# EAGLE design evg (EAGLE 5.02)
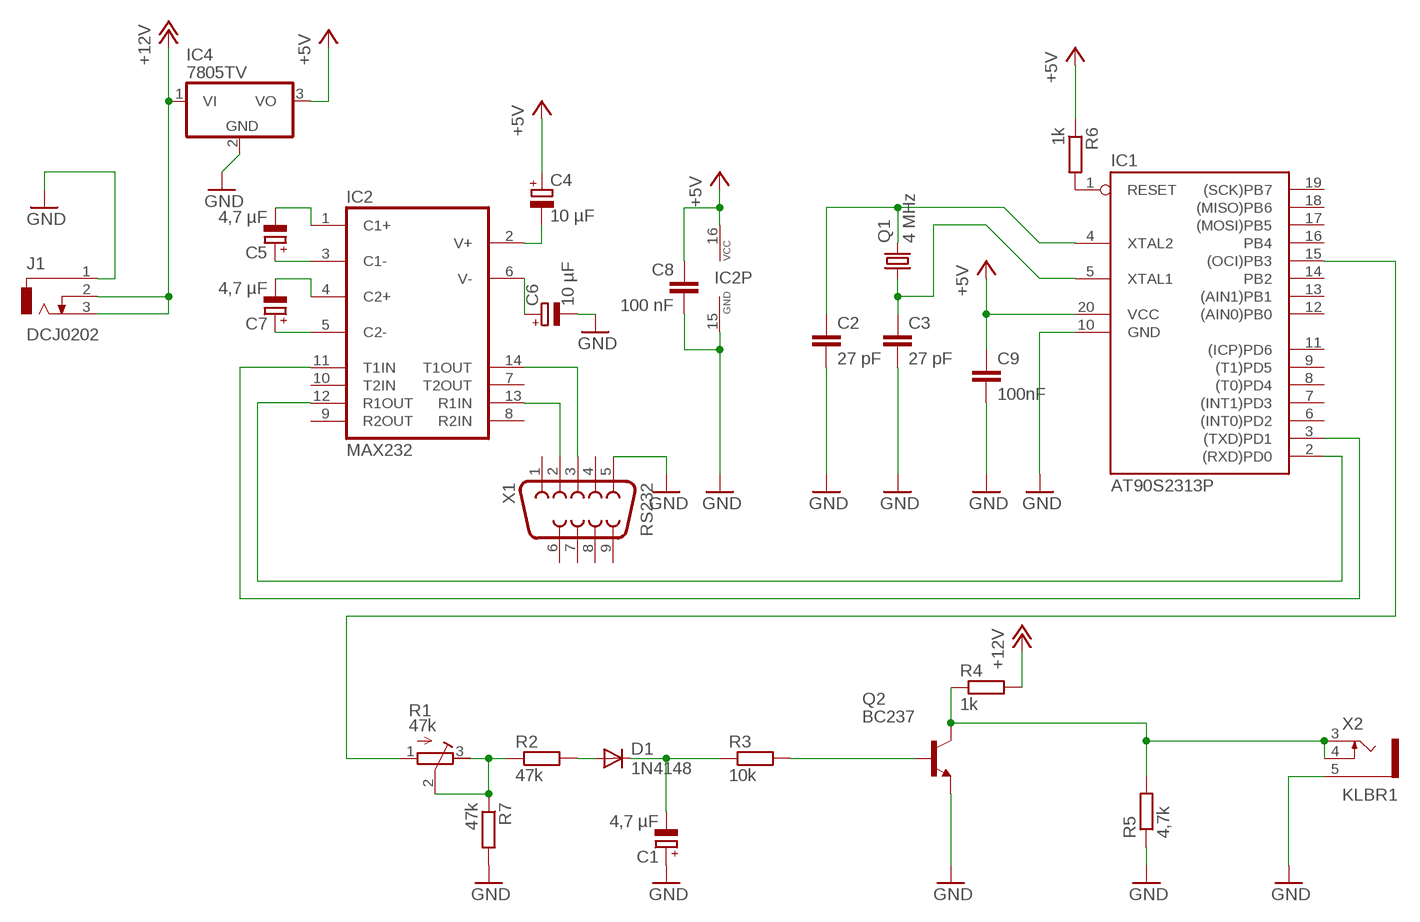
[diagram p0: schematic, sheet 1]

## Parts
C1  4,7 µF  CPOL-EUE2.5-6  [E2,5-6]
C2  27 pF  C-EU075-032X103  [C075-032X103]
C3  27 pF  C-EU075-032X103  [C075-032X103]
C4  10 µF  CPOL-EUE2.5-6  [E2,5-6]
C5  4,7 µF  CPOL-EUE2.5-6  [E2,5-6]
C6  10 µF  CPOL-EUE2.5-6  [E2,5-6]
C7  4,7 µF  CPOL-EUE2.5-6  [E2,5-6]
C8  100 nF  C-EU075-032X103  [C075-032X103]
C9  100nF  C-EU075-032X103  [C075-032X103]
D1  1N4148  [DO35-10]
IC1  AT90S2313P  [DIL20]
IC2  MAX232  [DIL16]
IC4  7805TV  [TO220V]
J1  DCJ0202  [DCJ0202]
Q1  4 MHz  CRYSTALHC18U-V  [HC18U-V]
Q2  BC237  [TO92]
R1  47k  R-TRIMM74W  [RTRIM74W]
R2  47k  R-EU_0204/7  [0204/7]
R3  10k  R-EU_0204/7  [0204/7]
R4  1k  R-EU_0207/15  [0207/15]
R5  4,7k  R-EU_0204/7  [0204/7]
R6  1k  R-EU_0204/7  [0204/7]
R7  47k  R-EU_0204/7  [0204/7]
X1  RS232  F09H  [F09H]
X2  KLBR1  [KLBR1]

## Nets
+5V [supply]: C4.+ C8.1 C9.1 IC1.20(VCC) IC2.16(VCC) IC4.3(VO) R6.1
+12V [supply]: IC4.1(VI) J1.2 J1.3 R4.2
C6: C6.+ IC2.6(V-)
GND [supply]: C1.+ C2.2 C3.2 C6.- C8.2 C9.2 IC1.10(GND) IC2.15(GND) IC4.2(GND) J1.1 Q2.1(E) R5.1 R7.2 X1.5 X2.5
N$1: IC1.2((RXD)PD0) IC2.12(R1OUT)
N$2: IC1.1(RESET) R6.2
N$3: IC1.3((TXD)PD1) IC2.11(T1IN)
N$4: C7.+ IC2.5(C2-)
N$5: C5.+ IC2.3(C1-)
N$6: C2.1 IC1.4(XTAL2) Q1.2
N$7: C7.- IC2.4(C2+)
N$8: C5.- IC2.1(C1+)
N$9: C4.- IC2.2(V+)
N$11: C3.1 IC1.5(XTAL1) Q1.1
N$13: IC2.13(R1IN) X1.2
N$14: IC2.14(T1OUT) X1.3
N$15: Q2.3(C) R4.1 R5.2 X2.3 X2.4
N$16: D1.A R2.2
N$17: R1.2(S) R1.3(A) R2.1 R7.1
N$18: C1.- D1.C R3.1
N$19: Q2.2(B) R3.2
N$23: IC1.15((OCI)PB3) R1.1(E)
Unconnected: IC1.6((INT0)PD2) IC1.7((INT1)PD3) IC1.8((T0)PD4) IC1.9((T1)PD5) IC1.11((ICP)PD6) IC1.12((AIN0)PB0) IC1.13((AIN1)PB1) IC1.14(PB2) IC1.16(PB4) IC1.17((MOSI)PB5) IC1.18((MISO)PB6) IC1.19((SCK)PB7) IC2.7(T2OUT) IC2.8(R2IN) IC2.9(R2OUT) IC2.10(T2IN) X1.1 X1.4 X1.6 X1.7 X1.8 X1.9

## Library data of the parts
C1 C4-C7 = resistor:CPOL-EU: POLARIZED CAPACITOR, European symbol
C2 C3 C8 C9 = resistor:C-EU: CAPACITOR, European symbol
D1 = diode:1N4148: DIODE
IC1 = atmel:AT90S2313: MICROCONTROLLER 2 Kbytes FLASH 128 bytes SRAM 128 bytes EEPROM UART
IC2 = maxim:MAX232: RS232 TRANSEIVER
IC4 = linear:78*: Positive VOLTAGE REGULATOR Source: http://cache.national.com/ds/LM/LM78L05.pdf http://www.fairchildsemi.com/ds/LM/LM7805.pdf
J1 = con-jack:DCJ0202: DC POWER JACK Source: DCJ0202.pdf
Q1 = crystal:CRYSTAL: CRYSTAL
Q2 = transistor-npn:BC237: NPN Transistor
R1 = resistor:R-TRIMM: Trimm resistor
R2-R7 = resistor:R-EU_: RESISTOR, European symbol
X1 = con-subd:F09: SUB-D
X2 = con-lumberg:KLBR?: Jack connectors according to JISC 6560, 2.5mm / 3.5 mm Klinkensteckverbinder nach JISC 6560, 2.5mm / 3,5 mm Source: http://www.lumberg.com/Produkte/PDFs/KLBR2.pdf www.lumberg.com/Produkte/PDFs/KLBR1.pdf

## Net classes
0 default: width 0.406 mm
1 supply: width 1.143 mm

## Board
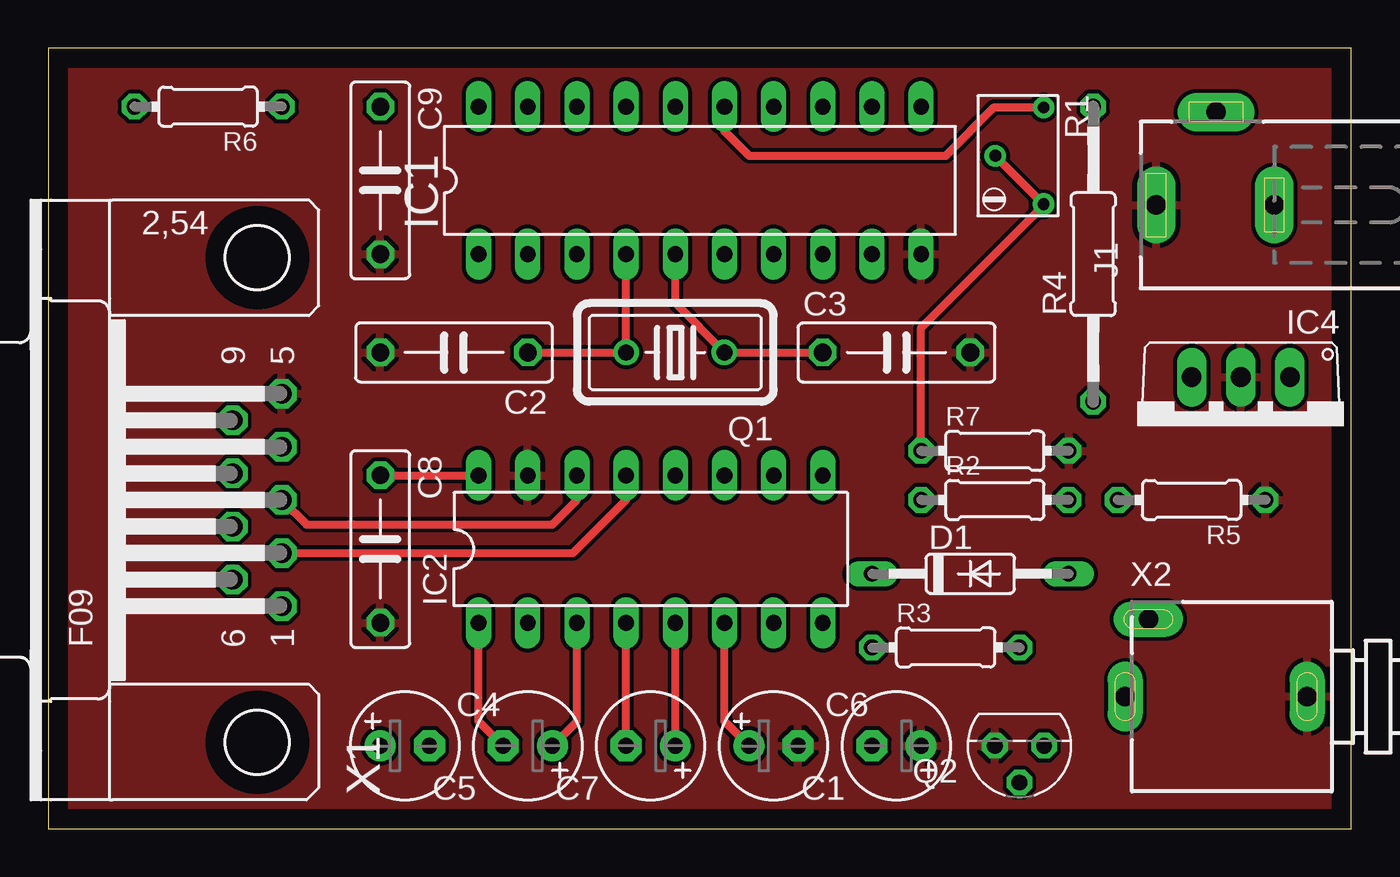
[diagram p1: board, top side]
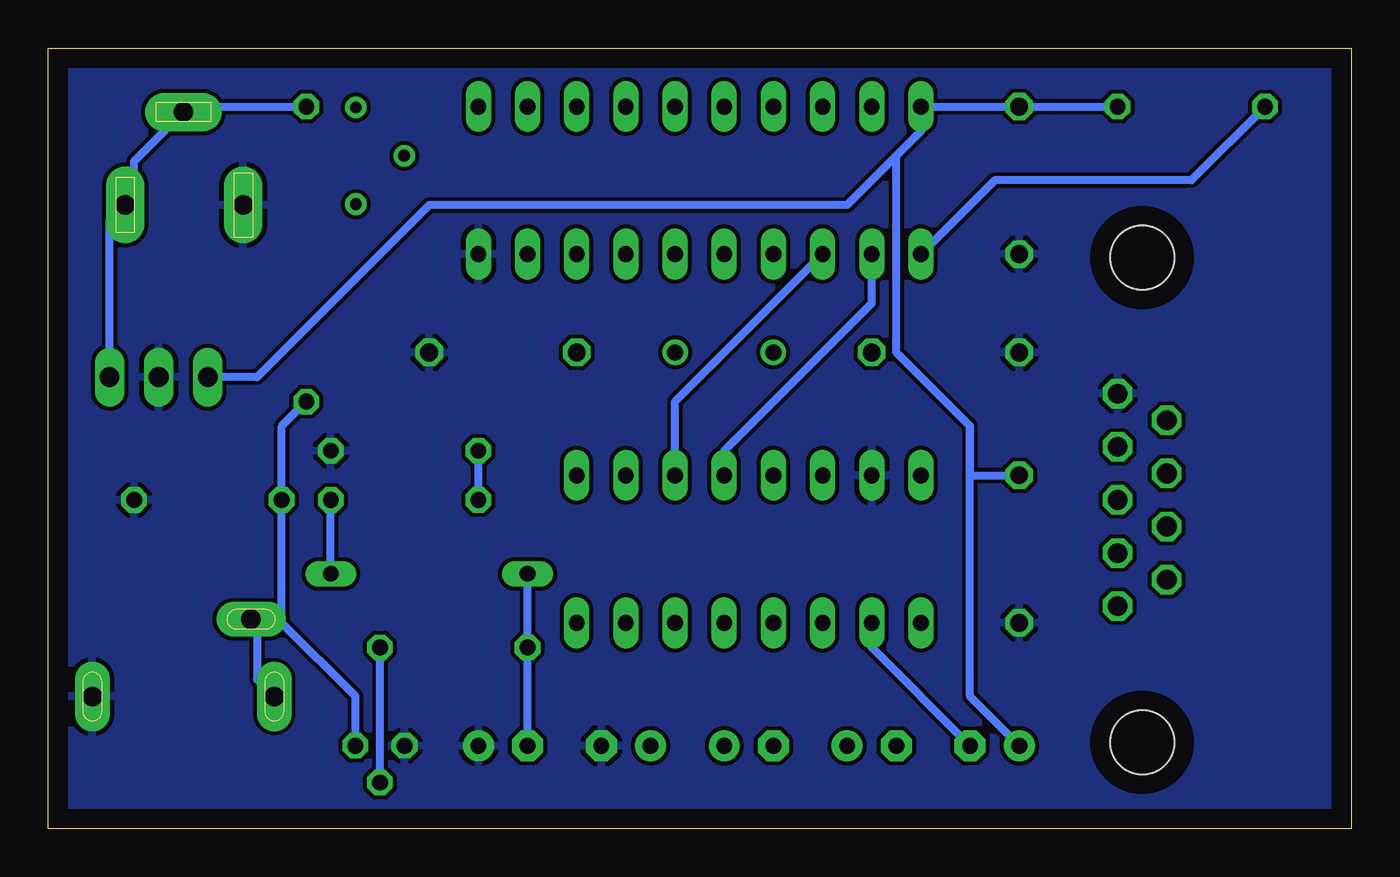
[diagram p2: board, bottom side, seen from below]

Size 67.29 x 40.31 mm. Coordinates in mm from the lower left corner, seen from the top.
Outline: 0,0 67.29,0 67.29,40.31 0,40.31 0,0
Copper layers (1*16): Top 0.035mm / dielectric 1.5mm / Bottom 0.035mm
Design rules "default": minimum track width 10mil, minimum drill 24mil, track to track 8mil, track to pad 8mil, pad to pad 8mil, via to via 8mil, smd to smd 8mil, copper to edge 40mil, drill to drill 8mil, minimum pad ring 10mil, minimum via ring 8mil, stop-mask expansion 4mil, vias tented up to drill 0mil, thermal gap 10mil

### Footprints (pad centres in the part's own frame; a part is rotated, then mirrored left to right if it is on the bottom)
E2,5-6 = drill 0.813 pad 1.6 round: + -1.27,0 | drill 0.813 pad 1.6 octagon: - 1.27,0
C075-032X103 = drill 0.914 octagon: 1 -3.81,0; 2 3.81,0
DO35-10 = drill 0.813 long: A 5.08,0; C -5.08,0
DIL20 = drill 0.813 long: 1 -11.43,-3.81; 2 -8.89,-3.81; 3 -6.35,-3.81; 4 -3.81,-3.81; 5 -1.27,-3.81; 6 1.27,-3.81; 7 3.81,-3.81; 8 6.35,-3.81; 9 8.89,-3.81; 10 11.43,-3.81; 11 11.43,3.81; 12 8.89,3.81; 13 6.35,3.81; 14 3.81,3.81; 15 1.27,3.81; 16 -1.27,3.81; 17 -3.81,3.81; 18 -6.35,3.81; 19 -8.89,3.81; 20 -11.43,3.81
DIL16 = drill 0.813 long: 1 -8.89,-3.81; 2 -6.35,-3.81; 3 -3.81,-3.81; 4 -1.27,-3.81; 5 1.27,-3.81; 6 3.81,-3.81; 7 6.35,-3.81; 8 8.89,-3.81; 9 8.89,3.81; 10 6.35,3.81; 11 3.81,3.81; 12 1.27,3.81; 13 -1.27,3.81; 14 -3.81,3.81; 15 -6.35,3.81; 16 -8.89,3.81
TO220V = drill 1.016 long: 1 -2.54,-2.54; 2 0,-2.54; 3 2.54,-2.54
DCJ0202 = drill 1 pad 2 long: 1 0,3.1; 2 4.8,0; 3 0,-3
HC18U-V = drill 0.813 round: 1 -2.54,0; 2 2.54,0
TO92 = drill 0.813 octagon: 1 1.27,0; 2 0,1.905; 3 -1.27,0
RTRIM74W = drill 0.61 round: 1 -1.25,-2.5; 2 1.25,0; 3 -1.25,2.5
0204/7 = drill 0.813 octagon: 1 -3.81,0; 2 3.81,0
0207/15 = drill 0.813 octagon: 1 -7.62,0; 2 7.62,0
F09H = drill 1.016 octagon: 1 -5.486,-1.27; 2 -2.743,-1.27; 3 0,-1.27; 4 2.743,-1.27; 5 5.486,-1.27; 6 -4.115,1.27; 7 -1.372,1.27; 8 1.372,1.27; 9 4.115,1.27 | hole 3.302: -12.522,0; 12.522,0
KLBR1 = drill 1 pad 1.8 long: 3 0,-4.7; 4 -4,-3.5; 5 0,4.7

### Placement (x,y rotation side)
C1  43.81,4.28 180 top
C2  20.95,24.6 180 top
C3  43.81,24.6 0 top
C4  18.41,4.28 0 top
C5  24.76,4.28 180 top
C6  37.46,4.28 0 top
C7  31.11,4.28 180 top
C8  17.14,14.44 270 top
C9  17.14,33.49 270 top
D1  47.62,13.17 0 top
IC1  33.65,33.49 0 top
IC2  31.11,14.44 0 top
IC4  61.59,20.79 180 top
J1  60.32,32.22 90 top
Q1  32.38,24.6 180 top
Q2  50.16,4.28 180 top
R1  50.16,34.76 180 top
R2  48.89,16.98 0 top
R3  46.35,9.36 0 top
R4  53.97,29.68 90 top
R5  59.05,16.98 180 top
R6  8.25,37.3 180 top
R7  48.89,19.52 0 top
X1  10.79,16.98 90 top
X2  60.32,6.82 270 top

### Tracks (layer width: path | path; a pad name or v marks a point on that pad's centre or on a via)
+5V
  Top 0.406: C8.1 IC2.16
  Bottom 0.406: 23.49,34.76 22.22,36.03 IC1.20 C9.1 R6.1 | 23.49,34.76 26.03,32.22 47.62,32.22 56.51,23.33 IC4.3 | C4.+ 19.68,6.82 19.68,20.79 | 19.68,20.79 23.49,24.6 23.49,34.76 | 19.68,20.79 19.68,18.25 C8.1
+12V
  Bottom 0.406: IC4.1 64.13,31.41 J1.3 62.86,32.22 62.86,34.48 J1.2 60.32,37.3 R4.2
C6
  Top 0.406: IC2.6 34.92,5.55 C6.+
GND
  pour Top: -1.91,42.38 -1.91,-2.07 71.75,-2.07 71.75,42.38
  pour Bottom: -0.64,41.11 -0.64,-0.8 70.48,-0.8 70.48,41.11
N$1
  Bottom 0.406: IC1.2 24.76,27.14 32.38,19.52 IC2.12
N$2
  Bottom 0.406: R6.2 8.25,33.49 18.41,33.49 IC1.1
N$3
  Bottom 0.406: IC1.3 34.92,22.06 IC2.11
N$4
  Top 0.406: C7.+ IC2.5
N$5
  Top 0.406: IC2.3 27.3,5.55 C5.+
N$6
  Top 0.406: IC1.4 Q1.2 C2.1
N$7
  Top 0.406: C7.- IC2.4
N$8
  Top 0.406: IC2.1 22.22,5.55 C5.-
N$9
  Bottom 0.406: C4.- 24.76,9.36 IC2.2
N$11
  Top 0.406: IC1.5 32.38,27.14 Q1.1 C3.1
N$13
  Top 0.406: X1.2 27.1,14.24 29.84,16.98 IC2.13
N$14
  Top 0.406: X1.3 13.33,15.71 26.03,15.71 27.3,16.98 IC2.14
N$15
  Bottom 0.406: Q2.3 51.43,6.82 55.24,10.63 | 55.24,10.63 R5.2 55.24,20.79 R4.1 | 55.24,10.63 56.51,10.63 | 56.51,10.63 56.63,10.63 X2.4 | X2.3 56.51,7.71 56.51,10.63
N$16
  Bottom 0.406: D1.A R2.2
N$17
  Top 0.406: R7.1 45.08,25.87 51.43,32.22 51.41,32.24 R1.3 51.39,32.26 48.89,34.76 R1.2
  Bottom 0.406: R2.1 R7.1
N$18
  Bottom 0.406: C1.- R3.1 D1.C
N$19
  Bottom 0.406: Q2.2 R3.2
N$23
  Top 0.406: R1.1 48.85,37.26 46.35,34.76 36.19,34.76 34.92,36.03 IC1.15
